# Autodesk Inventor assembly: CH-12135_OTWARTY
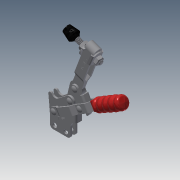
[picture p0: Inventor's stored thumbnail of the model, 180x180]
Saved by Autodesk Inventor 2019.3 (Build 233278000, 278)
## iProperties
Company: Î¢ÈíÖÐ¹ú
Created: 2012-09
Part Number: CH-12135_OTWARTY
Material: Ogólny
Description: STEP AP203
Document SubType Name: Assembly
Designer: CADENGINEERING4
Sending System: SolidWorks 2010
Preprocessor: SwSTEP 2.0
Title: CH-12135.STEP
Author: Î¢ÈíÓÃ»§
Revision Number: ÈÎºÎ
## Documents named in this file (12)
- D:\Vault_2016\Projekty\STRONA\Vertical toggle clamp\Do zrobienia 3\CH-12135\CH-12135_OTWARTY.iam
- D:\Vault_2016\Projekty\STRONA\Vertical toggle clamp\Do zrobienia 3\CH-12135\CH-12130-05.ipt
- D:\Vault_2016\Projekty\STRONA\Vertical toggle clamp\Do zrobienia 3\CH-12135\CH-12130-04 CONNECTING-PLATE.ipt
- D:\Vault_2016\Projekty\STRONA\Vertical toggle clamp\Do zrobienia 3\CH-12135\CH-12130-08.ipt
- D:\Vault_2016\Projekty\STRONA\Vertical toggle clamp\Do zrobienia 3\CH-12135\CH-FW-516.ipt
- D:\Vault_2016\Projekty\STRONA\Vertical toggle clamp\Do zrobienia 3\CH-12135\CH-FC-56212 Nut.ipt
- D:\Vault_2016\Projekty\STRONA\Vertical toggle clamp\Do zrobienia 3\CH-12135\CH-12130-03 STRAIGHT HANDLE.ipt
- D:\Vault_2016\Projekty\STRONA\Vertical toggle clamp\Do zrobienia 3\CH-12135\CH-FC-56212 SPINDLE SUPPLIED.ipt
- D:\Vault_2016\Projekty\STRONA\Vertical toggle clamp\Do zrobienia 3\CH-12135\CH-12130-06.ipt
- D:\Vault_2016\Projekty\STRONA\Vertical toggle clamp\Do zrobienia 3\CH-12135\CH-12130-07.ipt
- D:\Vault_2016\Projekty\STRONA\Vertical toggle clamp\Do zrobienia 3\CH-12135\CH-12135-02 SHORT U-BAR.ipt
- D:\Vault_2016\Projekty\STRONA\Vertical toggle clamp\Do zrobienia 3\CH-12135\CH-12135-01 STRAIGHT BASE.ipt
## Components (15 placed, 11 different names)
1. CH-12135-01 STRAIGHT BASE_15
2. CH-12130-05:2 — Zestawiające:1, Równoległe:2
3. CH-12130-04 CONNECTING-PLATE:2 — Zestawiające:5, Zestawiające:7, Zestawiające:8, Zestawiające:9, Zestawiające:10, Zestawiające:12, Zestawiające:14, Zestawiające:15, Zestawiające:16, Zestawiające:20
4. CH-12130-08:3 — Zestawiające:1, Zestawiające:2, Zestawiające:3, Zestawiające:4
5. CH-FW-516:3 — Zestawiające:23, Zestawiające:26, Zestawiające:28
6. CH-FC-56212 Nut:3 — Zestawiające:22, Zestawiające:27, Zestawiające:29, Zestawiające:30
7. CH-FW-516:4 — Zestawiające:24, Zestawiające:25, Zestawiające:27
8. CH-12130-03 STRAIGHT HANDLE:2 — Zestawiające:2, Zestawiające:3, Zestawiające:4, Zestawiające:17, Zestawiające:18, Zestawiające:19, Zestawiające:20, Zestawiające:31, Zestawiające:32, Zestawiające:33
9. CH-FC-56212 SPINDLE SUPPLIED:2 — Zestawiające:21, Równoległe:1
10. CH-12130-06:3 — Zestawiające:5, Zestawiające:6, Zestawiające:7, Zestawiające:8, Zestawiające:10, Zestawiające:11, Zestawiające:12
11. CH-FC-56212 Nut:4 — Zestawiające:21, Zestawiające:22, Zestawiające:23, Zestawiające:24, Zestawiające:28
12. CH-12130-08:4 — Zestawiające:15, Zestawiające:16, Zestawiające:17, Zestawiające:18, Zestawiające:19
13. CH-12130-06:4 — Zestawiające:13, Zestawiające:14
14. CH-12130-07:2 — Zestawiające:31, Zestawiające:32, Zestawiające:33
15. CH-12135-02 SHORT U-BAR:2 — Zestawiające:6, Zestawiające:9, Zestawiające:11, Zestawiające:13, Zestawiające:25, Zestawiające:26, Równoległe:1, Zestawiające:29, Zestawiające:30, Równoległe:2
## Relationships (35: Mate 33, Flush 2)
- Zestawiające:1 [Mate]: CH-12130-05:2 ↔ CH-12130-08:3
- Zestawiające:2 [Mate]: CH-12130-08:3 ↔ CH-12130-03 STRAIGHT HANDLE:2
- Zestawiające:3 [Mate]: CH-12130-08:3 ↔ CH-12130-03 STRAIGHT HANDLE:2
- Zestawiające:4 [Mate]: CH-12130-08:3 ↔ CH-12130-03 STRAIGHT HANDLE:2
- Zestawiające:5 [Mate]: CH-12130-04 CONNECTING-PLATE:2 ↔ CH-12130-06:3
- Zestawiające:6 [Mate]: CH-12130-06:3 ↔ CH-12135-02 SHORT U-BAR:2
- Zestawiające:7 [Mate]: CH-12130-04 CONNECTING-PLATE:2 ↔ CH-12130-06:3
- Zestawiające:8 [Mate]: CH-12130-04 CONNECTING-PLATE:2 ↔ CH-12130-06:3
- Zestawiające:9 [Mate]: CH-12130-04 CONNECTING-PLATE:2 ↔ CH-12135-02 SHORT U-BAR:2
- Zestawiające:10 [Mate]: CH-12130-04 CONNECTING-PLATE:2 ↔ CH-12130-06:3
- Zestawiające:11 [Mate]: CH-12130-06:3 ↔ CH-12135-02 SHORT U-BAR:2
- Zestawiające:12 [Mate]: CH-12130-04 CONNECTING-PLATE:2 ↔ CH-12130-06:3
- Zestawiające:13 [Mate]: CH-12130-06:4 ↔ CH-12135-02 SHORT U-BAR:2
- Zestawiające:14 [Mate]: CH-12130-04 CONNECTING-PLATE:2 ↔ CH-12130-06:4
- Zestawiające:15 [Mate]: CH-12130-04 CONNECTING-PLATE:2 ↔ CH-12130-08:4
- Zestawiające:16 [Mate]: CH-12130-04 CONNECTING-PLATE:2 ↔ CH-12130-08:4
- Zestawiające:17 [Mate]: CH-12130-03 STRAIGHT HANDLE:2 ↔ CH-12130-08:4
- Zestawiające:18 [Mate]: CH-12130-03 STRAIGHT HANDLE:2 ↔ CH-12130-08:4
- Zestawiające:19 [Mate]: CH-12130-03 STRAIGHT HANDLE:2 ↔ CH-12130-08:4
- Zestawiające:20 [Mate]: CH-12130-04 CONNECTING-PLATE:2 ↔ CH-12130-03 STRAIGHT HANDLE:2
- Zestawiające:21 [Mate]: CH-FC-56212 SPINDLE SUPPLIED:2 ↔ CH-FC-56212 Nut:4
- Zestawiające:22 [Mate]: CH-FC-56212 Nut:3 ↔ CH-FC-56212 Nut:4
- Zestawiające:23 [Mate]: CH-FW-516:3 ↔ CH-FC-56212 Nut:4
- Zestawiające:24 [Mate]: CH-FW-516:4 ↔ CH-FC-56212 Nut:4
- Zestawiające:25 [Mate]: CH-FW-516:4 ↔ CH-12135-02 SHORT U-BAR:2
- Zestawiające:26 [Mate]: CH-FW-516:3 ↔ CH-12135-02 SHORT U-BAR:2
- Zestawiające:27 [Mate]: CH-FC-56212 Nut:3 ↔ CH-FW-516:4
- Zestawiające:28 [Mate]: CH-FW-516:3 ↔ CH-FC-56212 Nut:4
- Równoległe:1 [Flush]: CH-FC-56212 SPINDLE SUPPLIED:2 ↔ CH-12135-02 SHORT U-BAR:2
- Zestawiające:29 [Mate]: CH-FC-56212 Nut:3 ↔ CH-12135-02 SHORT U-BAR:2
- Zestawiające:30 [Mate]: CH-FC-56212 Nut:3 ↔ CH-12135-02 SHORT U-BAR:2
- Zestawiające:31 [Mate]: CH-12130-03 STRAIGHT HANDLE:2 ↔ CH-12130-07:2
- Zestawiające:32 [Mate]: CH-12130-03 STRAIGHT HANDLE:2 ↔ CH-12130-07:2
- Zestawiające:33 [Mate]: CH-12130-03 STRAIGHT HANDLE:2 ↔ CH-12130-07:2
- Równoległe:2 [Flush]: CH-12130-05:2 ↔ CH-12135-02 SHORT U-BAR:2
